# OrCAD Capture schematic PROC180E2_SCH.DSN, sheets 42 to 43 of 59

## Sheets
42 33. POWER SUPPLY FOR ETHERNET: size C; title: POWER SUPPLY (CORE) FOR ETHERNET PHY
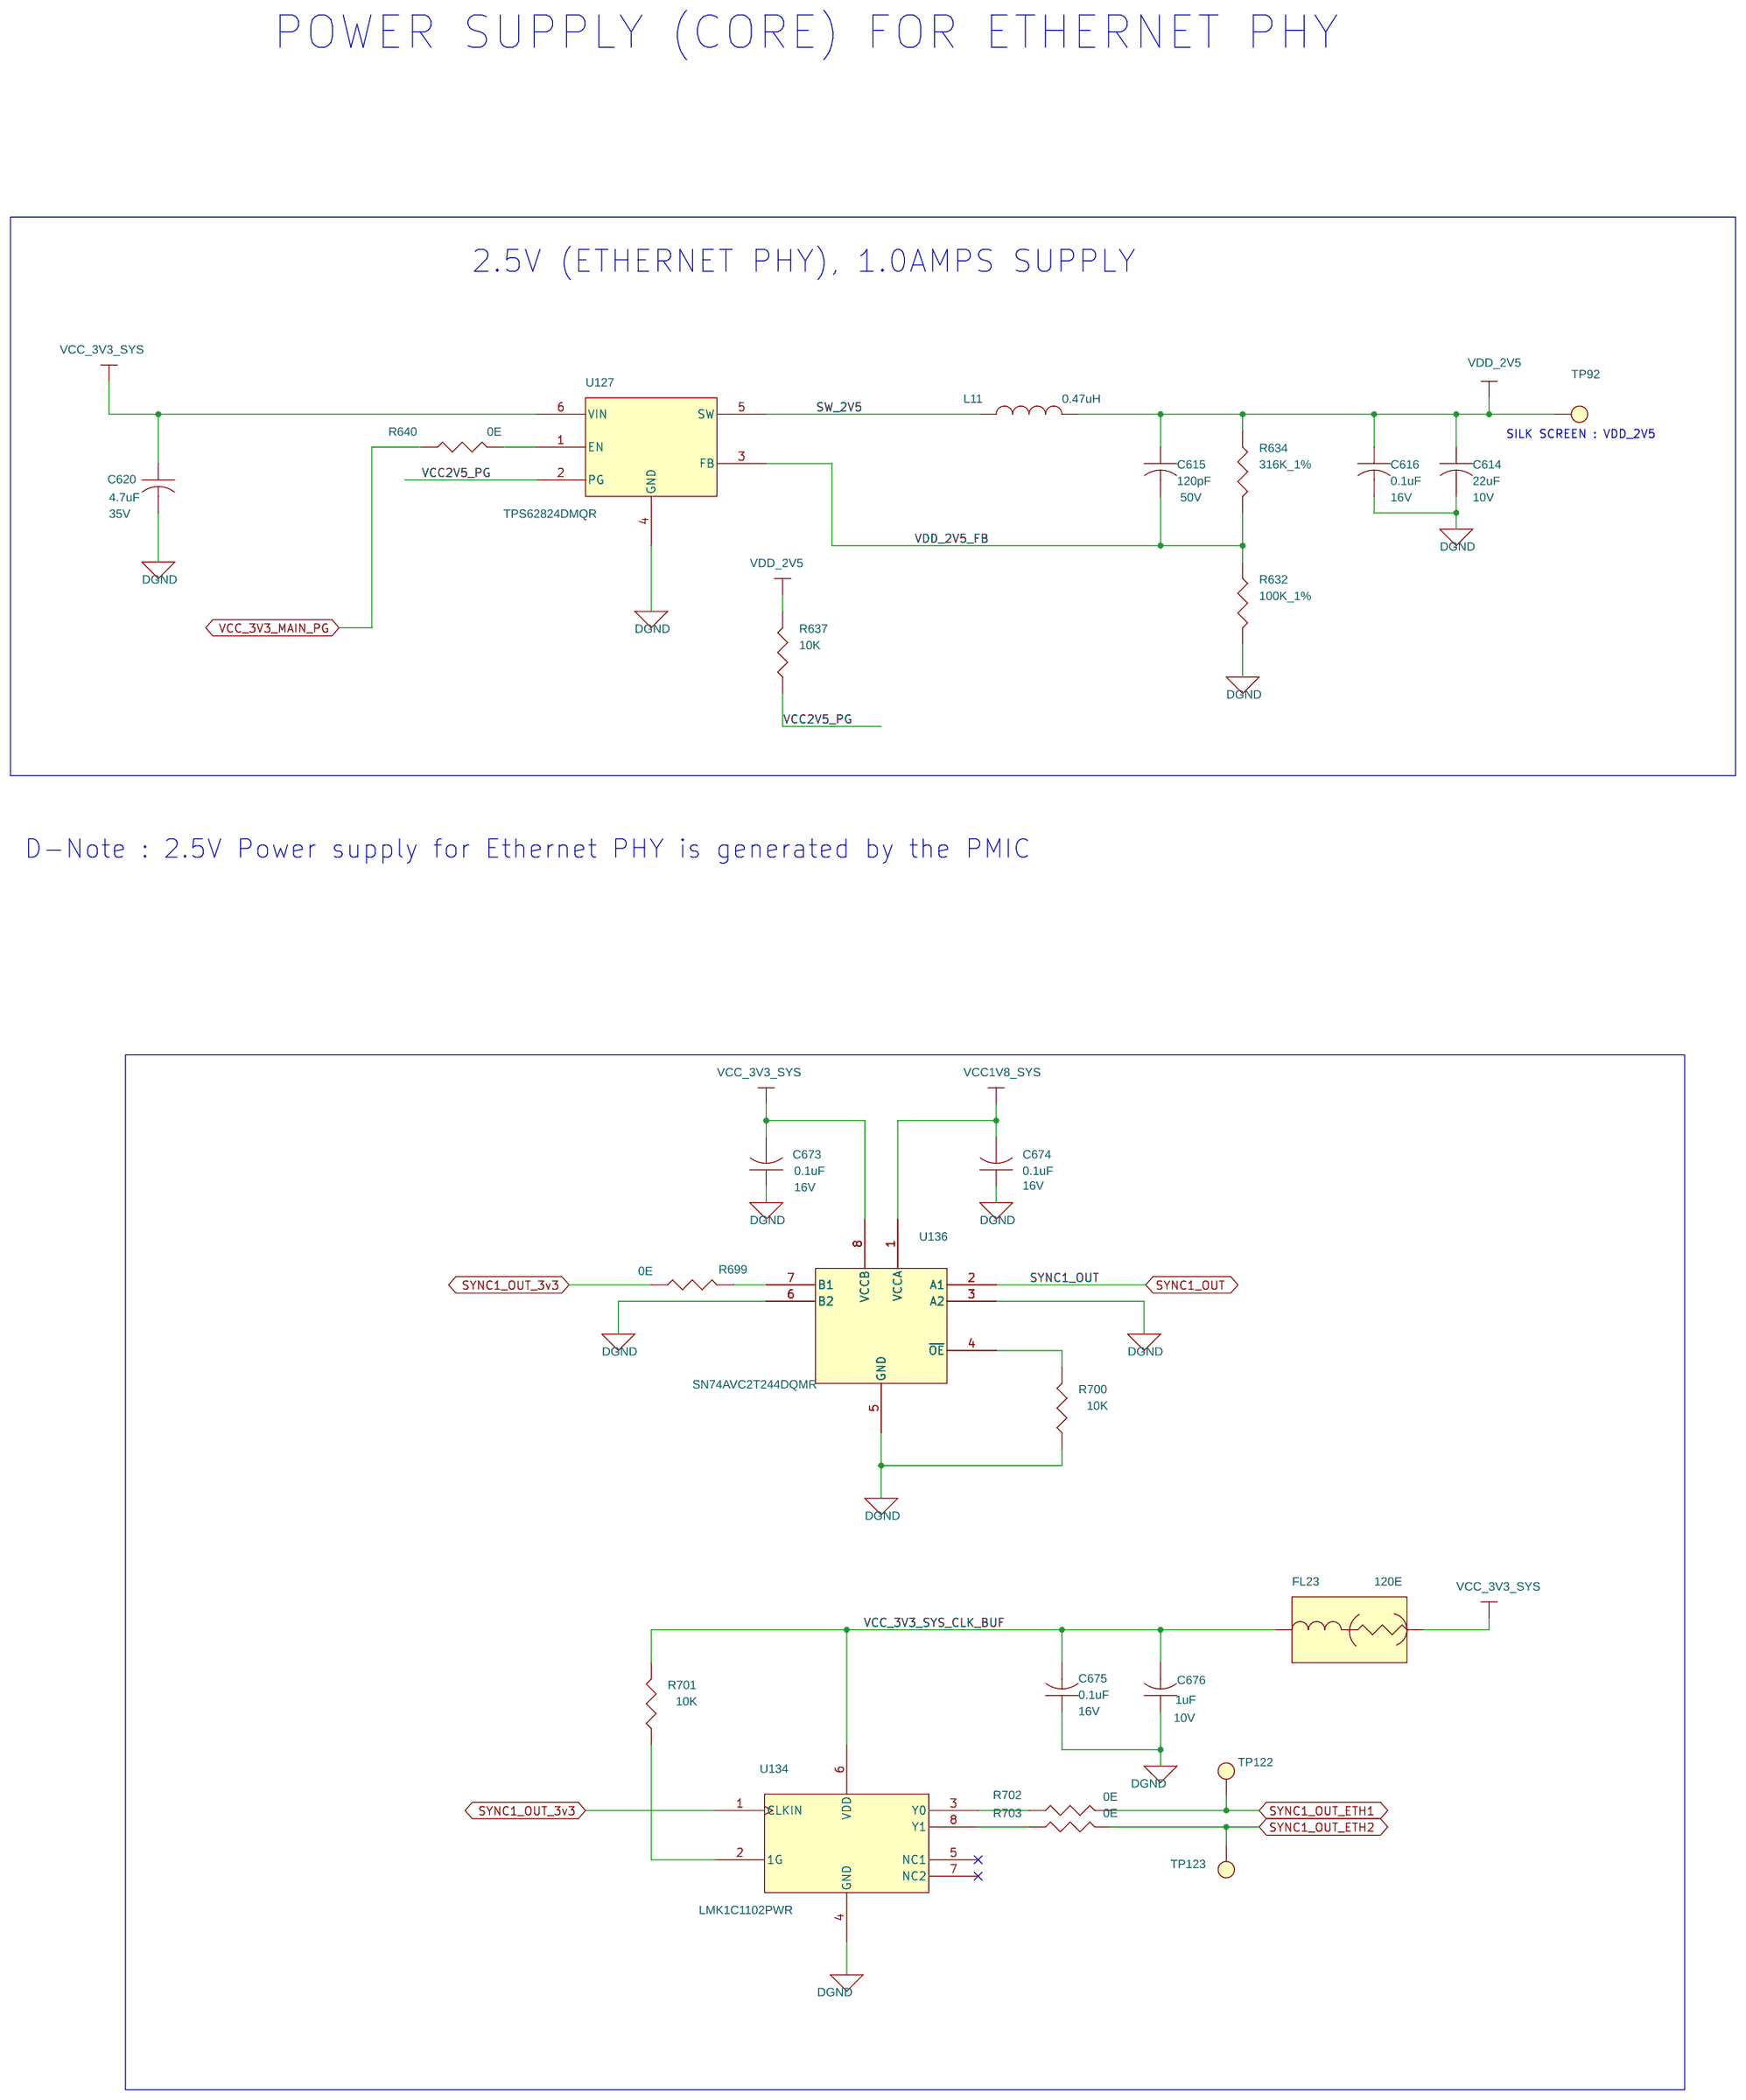
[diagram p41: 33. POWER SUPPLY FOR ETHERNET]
43 48. BOOTMODE BUFFERS AND IO EXP: size C; title: BOOT MODE BUFFER & IO EXPANDERS
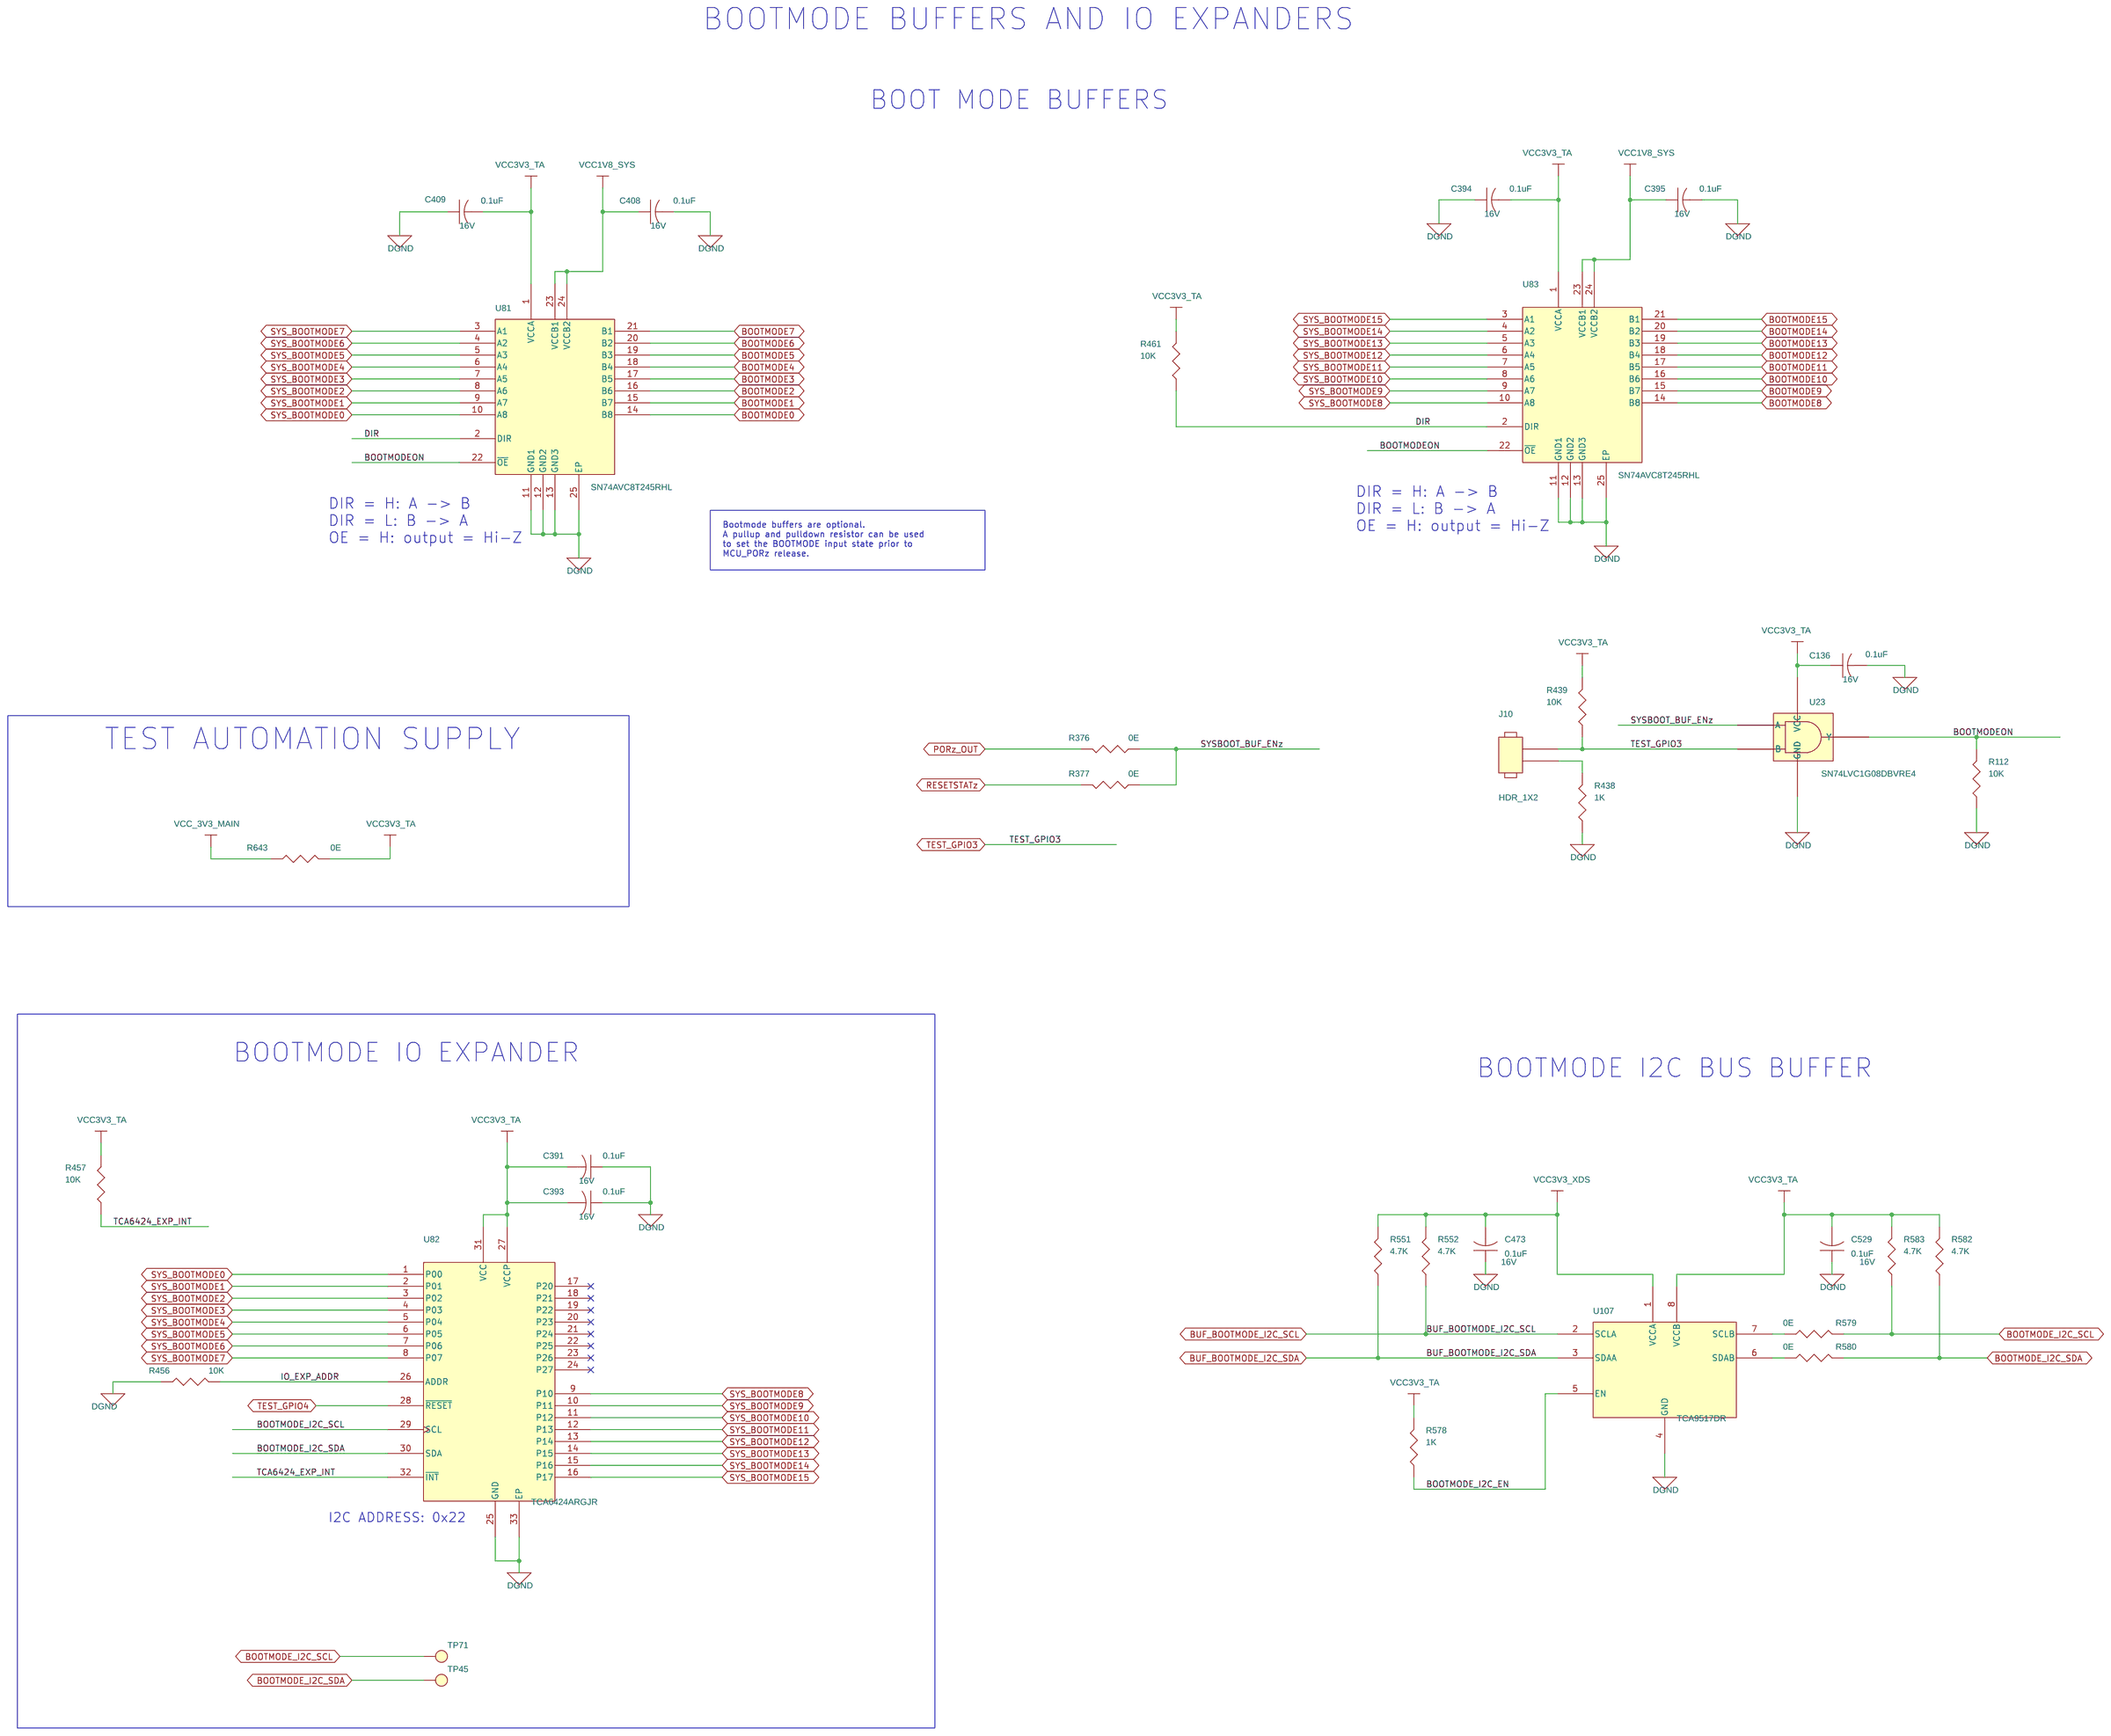
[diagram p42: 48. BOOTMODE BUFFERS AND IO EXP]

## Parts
sheet 33. POWER SUPPLY FOR ETHERNET
C614  22uF  [CAP0603_1]
C615  120pF  [CAP0201_0-5]
C616  0.1uF  [CAP0201_0-5]
C620  4.7uF  [CAP0603_1]
C673  0.1uF  [CAP0201_0-5]
C674  0.1uF  [CAP0201_0-5]
C675  0.1uF  [CAP0201_0-5]
C676  1uF  [CAP0201_0-5]
FL23  120E  [EMIFIL_BLM15A_0402_0-6]
L11  0.47uH  [IND0806_1-2]
R632  100K_1%  [RES0402_0-5]
R634  316K_1%  [RES0402_0-5]
R637  10K  [RES0201_0-5]
R640  0E  [RES0201_0-5]
R699  0E  [RES0201_0-5]
R700  10K  [RES0201_0-5]
R701  10K  [RES0201_0-5]
R702  0E  [RES0201_0-5]
R703  0E  [RES0201_0-5]
TP92  TP20_SMD  [TP20_SMD]
TP122  TP20_SMD  [TP20_SMD]
TP123  TP20_SMD  [TP20_SMD]
U127  TPS62824DMQR  [VSONHR6_TPS62826_60X60_1]
U134  LMK1C1102PWR  [TSSOP8_25-59_125X180_1-2]
U136  SN74AVC2T244DQMR  [X2SON8_15-74_70X50]
sheet 48. BOOTMODE BUFFERS AND IO EXP
C136  0.1uF  [CAP0201_0-5]
C391  0.1uF  [CAP0201_0-5]
C393  0.1uF  [CAP0201_0-5]
C394  0.1uF  [CAP0201_0-5]
C395  0.1uF  [CAP0201_0-5]
C408  0.1uF  [CAP0201_0-5]
C409  0.1uF  [CAP0201_0-5]
C473  0.1uF  [CAP0201_0-5]
C529  0.1uF  [CAP0201_0-5]
J10  HDR_1X2  [HDR_1X2_90120-0122_S_T_5-6]
R112  10K  [RES0201_0-5]
R376  0E  [RES0201_0-5]
R377  0E  [RES0201_0-5]
R438  1K  [RES0201_0-5]
R439  10K  [RES0201_0-5]
R456  10K  [RES0201_0-5]
R457  10K  [RES0201_0-5]
R461  10K  [RES0201_0-5]
R551  4.7K  [RES0201_0-5]
R552  4.7K  [RES0201_0-5]
R578  1K  [RES0402_0-5]
R579  0E  [RES0201_0-5]
R580  0E  [RES0201_0-5]
R582  4.7K  [RES0201_0-5]
R583  4.7K  [RES0201_0-5]
R643  0E  [RES0805_0-75]
TP45  TP20_SMD  [TP20_SMD]
TP71  TP20_SMD  [TP20_SMD]
U23  SN74LVC1G08DBVRE4  [SOT23-5]
U81  SN74AVC8T245RHL  [QFN24_19-68_220X140_1]
U82  TCA6424ARGJR  [QFN32_19-68_200X200]
U83  SN74AVC8T245RHL  [QFN24_19-68_220X140_1]
U107  TCA9517DR  [SOIC8_1-8]

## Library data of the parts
C614 = CAP: CAP CERAMIC 22uF 10V 20% X5R AUTO 0603; Chkd/date: MANIRAJA/250221; Crtd /date: ALVY/240221; Custom_Duty: 15%; Customs_HS_Code: 85369090; Distributor_name: MOUSER; Distributor_part_number: 81-GRT188R61A226ME13; Footprint Path: Y:\MIS_DATABASE\Library\ALTIUM_TOOL\PCB_FOOTPRINTS\Altium_Footprint_Lib.PcbLib; Height: 1.00MM; Library Path: Y:\MIS_DATABASE\Library\ALTIUM_TOOL\SCHEMATICS_PARTS\MS_DISCRETE_Library.schlib; Mfr_name: MURATA; Mfr_part_number: GRT188R61A226ME13D; Mistral Part No: 120021020033-R; Package: 0603; Part_type: CAPACITORS\CERAMIC; Project: TI_DRA821 SK EVM BRD; RoHS: RoHS; Temperature: -55°C+85°C; Tolerance: 20%; Voltage: 10V; Wattage: NA; Weight: NA; Datasheet: Y:\MIS_DATABASE\DATASHEETS\CAPACITORS\GRT188R61A226ME13.PDF
C615 = CAP: CAP CERAMIC 120pF 50V 5% C0G(NP0) AUTO 0201; Chkd/date: MANIRAJA/311221; Crtd /date: ALVY/301221; Custom_Duty: 15%; Customs_HS_Code: 85322990; Distributor_name: MOUSER; Distributor_part_number: 81-GRT0335C1H121JA2D; Footprint Path: Y:\MIS_DATABASE\Library\ALTIUM_TOOL\PCB_FOOTPRINTS\Altium_Footprint_Lib.PcbLib; Height: 0.33MM; Library Path: Y:\MIS_DATABASE\Library\ALTIUM_TOOL\SCHEMATICS_PARTS\MS_DISCRETE_Library.schlib; Mfr_name: MURATA; Mfr_part_number: GRT0335C1H121JA02D; Mistral Part No: 120021120016-R; Package: 0201; Part_type: CAPACITORS\CERAMIC; Project: AM62Q_SKEVM_BRD; RoHS: RoHS; Temperature: -55°C+125°C; Tolerance: 5%; Voltage: 50V; Wattage: NA; Weight: 0.33mg; Datasheet: Y:\MIS_DATABASE\DATASHEETS\CAPACITORS\GRT0335C1H121JA02.PDF
C391 C393 C616 = CAP: CAP CERAMIC 0.1uF 16V 10% X7S AUTO 0201; Chkd/date: MANIRAJA/110321; Crtd /date: ALVY/110321; Custom_Duty: 15%; Customs_HS_Code: 85322990; Distributor_name: DIGIKEY; Distributor_part_number: 490-GRT033C71C104KE01DTR-ND; Footprint Path: Y:\MIS_DATABASE\Library\ALTIUM_TOOL\PCB_FOOTPRINTS\Altium_Footprint_Lib.PcbLib; Height: 0.33MM; Library Path: Y:\MIS_DATABASE\Library\ALTIUM_TOOL\SCHEMATICS_PARTS\MS_DISCRETE_Library.schlib; Mfr_name: MURATA; Mfr_part_number: GRT033C71C104KE01D; Mistral Part No: 120021030007-R; Package: 0201; Part_type: CAPACITORS\CERAMIC; Project: J7ES_SK_BRD; RoHS: RoHS; Temperature: -55°C+125°C; Tolerance: 10%; Voltage: 16V; Wattage: NA; Weight: 330mg; Datasheet: Y:\MIS_DATABASE\DATASHEETS\CAPACITORS\GRT033C71C104KE01.PDF
C620 = CAP: CAP CERAMIC 4.7uF 35V 10% X5R AUTO 0603; Chkd/date: MANIRAJA/311221; Crtd /date: ALVY/301221; Custom_Duty: 15%; Customs_HS_Code: 85369090; Distributor_name: DIGIKEY; Distributor_part_number: 490-12337-1-ND; Footprint Path: Y:\MIS_DATABASE\Library\ALTIUM_TOOL\PCB_FOOTPRINTS\Altium_Footprint_Lib.PcbLib; Height: 1.00MM; Library Path: Y:\MIS_DATABASE\Library\ALTIUM_TOOL\SCHEMATICS_PARTS\MS_DISCRETE_Library.schlib; Mfr_name: MURATA; Mfr_part_number: GRT188R6YA475KE13D; Mistral Part No: 120021120020-R; Package: 0603; Part_type: CAPACITORS\CERAMIC; Project: AM62Q_SKEVM_BRD; RoHS: RoHS; Temperature: -55°C+85°C; Tolerance: 10%; Voltage: 35V; Wattage: NA; Weight: 6.3mg; Datasheet: Y:\MIS_DATABASE\DATASHEETS\CAPACITORS\GRT188R6YA475KE13.PDF
C136 C394 C395 C408 C409 C473 C529 C673-C675 = CAP: CAP CERAMIC 0.1uF 16V 10% X7S AUTO 0201; Alt_Mfr_name: YAGEO AMERICA; Alt_Mfr_part_number: CC0402KRX5R8BB104; Chkd/date: MANIRAJA/110321; Crtd /date: ALVY/110321; Custom_Duty: 15%; Customs_HS_Code: 85322990; Distributor_name: DIGIKEY; Distributor_part_number: 490-GRT033C71C104KE01DTR-ND; Footprint Path: Y:\MIS_DATABASE\Library\ALTIUM_TOOL\PCB_FOOTPRINTS\Altium_Footprint_Lib.PcbLib; Height: 0.33MM; Library Path: Y:\MIS_DATABASE\Library\ALTIUM_TOOL\SCHEMATICS_PARTS\MS_DISCRETE_Library.schlib; Mfr_name: MURATA; Mfr_part_number: GRT033C71C104KE01D; Mistral Part No: 120021030007-R; Package: 0201; Part_type: CAPACITORS\CERAMIC; Project: J7ES_SK_BRD; RoHS: RoHS; Temperature: -55°C+125°C; Tolerance: 10%; Voltage: 16V; Wattage: NA; Weight: 330mg; Datasheet: Y:\MIS_DATABASE\DATASHEETS\CAPACITORS\GRT033C71C104KE01.PDF
C676 = CAP: CAP CERAMIC 1uF 10V 20% X6S 0201; Chkd/date: PRADEEP/130623; Crtd /date: PRADEEP/130623; Custom_Duty: 15%; Customs_HS_Code: 85322990; Distributor_name: DIGIKEY; Distributor_part_number: 490-GRT033C81A105ME13DTR-ND; Footprint Path: Y:\MIS_DATABASE\Library\ALTIUM_TOOL\PCB_FOOTPRINTS\Altium_Footprint_Lib.PcbLib; Height: 0.39MM; Library Path: Y:\MIS_DATABASE\Library\ALTIUM_TOOL\SCHEMATICS_PARTS\MS_DISCRETE_Library.schlib; Mfr_name: MURATA; Mfr_part_number: GRT033C81A105ME13D; Mistral Part No: 120022060020-R; Package: 0201; Part_type: CAPACITORS\CERAMIC; Project: AM62P_SK; RoHS: RoHS; Temperature: -55°C+105°C; Tolerance: 20%; Voltage: 10V; Wattage: NA; Weight: NA; Datasheet: Y:\MIS_DATABASE\DATASHEETS\CAPACITORS\GRT033C81A105ME13D.PDF
FL23 = EMIFILTER_IND: IND FERRITE BEAD CHIP 120E 2A 0402; Chkd/date: MANIRAJA/311221; Crtd /date: ALVY/301221; Custom_Duty: 24%; Customs_HS_Code: 85437099; Distributor_name: NA; Distributor_part_number: NA; Footprint Path: Y:\MIS_DATABASE\Library\ALTIUM_TOOL\PCB_FOOTPRINTS\Altium_Footprint_Lib.PcbLib; Height: 0.55MM; Library Path: Y:\MIS_DATABASE\Library\ALTIUM_TOOL\SCHEMATICS_PARTS\MS_FILTER_Library.schlib; Mfr_name: MURATA; Mfr_part_number: BLM15PX121SZ1B; Mistral Part No: 130021120017-R; Package: 0402; Part_type: INDUCTOR; Project: AM62Q_SKEVM_BRD; RoHS: RoHS; Temperature: -55°C+125°C; Tolerance: 25%; Voltage: NA; Wattage: NA; Weight: 1mg; Datasheet: Y:\MIS_DATABASE\DATASHEETS\DISCRETES\INDUCTORS\BLM-SER.PDF
L11 = INDUCTOR: IND CHIP 0.47uH 3.2A 20% 0806; Chkd/date: MANIRAJA/281221; Crtd /date: ALVY/281221; Custom_Duty: 24%; Customs_HS_Code: 85437099; Distributor_name: DIGIKEY; Distributor_part_number: 490-18076-1-ND; Footprint Path: Y:\MIS_DATABASE\Library\ALTIUM_TOOL\PCB_FOOTPRINTS\Altium_Footprint_Lib.PcbLib; Height: 1.20MM; Library Path: Y:\MIS_DATABASE\Library\ALTIUM_TOOL\SCHEMATICS_PARTS\MS_DISCRETE_Library.schlib; Mfr_name: MURATA; Mfr_part_number: DFE201612PD-R47M=P2; Mistral Part No: 130021120008-R; Package: 0806; Project: AM62Q_SKEVM_BRD; RoHS: RoHS; Temperature: -40°C+125°C; Tolerance: 20%; Voltage: NA; Wattage: NA; Weight: 18.8mg; Datasheet: Y:\MIS_DATABASE\DATASHEETS\DISCRETES\INDUCTORS\DFE201612PD.PDF
R632 = RESISTOR: RES 100K 1/10W 1% 0402; Chkd/date: VASANTHA/201216; Crtd /date: MAZHAR/130306; Custom_Duty: 15%; Customs_HS_Code: 85332119; Distributor_name: DIGIKEY; Distributor_part_number: P100KLCT-ND; Footprint Path: Y:\MIS_DATABASE\Library\ALTIUM_TOOL\PCB_FOOTPRINTS\Altium_Footprint_Lib.PcbLib; Height: 0.40MM; Library Path: Y:\MIS_DATABASE\Library\ALTIUM_TOOL\SCHEMATICS_PARTS\MS_DISCRETE_Library.schlib; Mfr_name: PANASONIC-ECG; Mfr_part_number: ERJ-2RKF1003X; Mistral Part No: 110009030187-R; Package: 0402; Part_type: RESISTORS\FIXED; Project: J32; RoHS: RoHS; Temperature: -55°C+155°C; Tolerance: 1%; Voltage: NA; Wattage: 1/10W; Weight: 0.8mg; Datasheet: Y:\MIS_DATABASE\DATASHEETS\RESISTORS\PAN-ERJSER_NOV17.PDF
R634 = RESISTOR: RES 316K 1/10W 1% 0402; Chkd/date: MAZHAR/110310; Crtd /date: MUDDU/080310; Custom_Duty: 15%; Customs_HS_Code: 85332119; Distributor_name: DIGIKEY; Distributor_part_number: P316KLCT-ND; Footprint Path: Y:\MIS_DATABASE\Library\ALTIUM_TOOL\PCB_FOOTPRINTS\Altium_Footprint_Lib.PcbLib; Height: 0.40MM; Library Path: Y:\MIS_DATABASE\Library\ALTIUM_TOOL\SCHEMATICS_PARTS\MS_DISCRETE_Library.schlib; Mfr_name: PANASONIC-ECG; Mfr_part_number: ERJ-2RKF3163X; Mistral Part No: 110010030027-R; Package: 0402; Part_type: RESISTORS\FIXED; Project: VME_DSP_SUITE; RoHS: RoHS; Temperature: -55°C+155°C; Tolerance: 1%; Voltage: NA; Wattage: 1/10W; Weight: 0.8mg; Datasheet: Y:\MIS_DATABASE\DATASHEETS\RESISTORS\PAN-ERJSER_NOV17.PDF
R112 R439 R456 R457 R461 R637 R700 R701 = RESISTOR: RES 10K 1/20W 5% 0201; Chkd/date: MANIRAJA/050517; Crtd /date: MANIRAJA/050517; Custom_Duty: 15%; Customs_HS_Code: 85332119; Distributor_name: DIGIKEY; Distributor_part_number: 311-10KNCT-ND; Footprint Path: Y:\MIS_DATABASE\Library\ALTIUM_TOOL\PCB_FOOTPRINTS\Altium_Footprint_Lib.PcbLib; Height: 0.26MM; Library Path: Y:\MIS_DATABASE\Library\ALTIUM_TOOL\SCHEMATICS_PARTS\MS_DISCRETE_Library.schlib; Mfr_name: YAGEO AMERICA; Mfr_part_number: RC0201JR-0710KL; Mistral Part No: 110010070051-R; Package: 0201; Part_type: RESISTORS\FIXED; Project: GOLDEN-I LITE; RoHS: RoHS; Temperature: -55°C+125°C; Tolerance: 5%; Voltage: NA; Wattage: 1/20W; Weight: 0.17mg; Datasheet: Y:\MIS_DATABASE\DATASHEETS\RESISTORS\RCXXXXL-SER_MAR18.PDF
R376 R377 R579 R580 R640 R699 R702 R703 = RESISTOR: RES 0E 1/20W 5% 0201; Chkd/date: NAVEED/301214; Crtd /date: MUDDU/120710; Custom_Duty: 15%; Customs_HS_Code: 85332119; Distributor_name: DIGIKEY; Distributor_part_number: 311-0.0NCT-ND; Footprint Path: Y:\MIS_DATABASE\Library\ALTIUM_TOOL\PCB_FOOTPRINTS\Altium_Footprint_Lib.PcbLib; Height: 0.26MM; Library Path: Y:\MIS_DATABASE\Library\ALTIUM_TOOL\SCHEMATICS_PARTS\MS_DISCRETE_Library.schlib; Mfr_name: YAGEO AMERICA; Mfr_part_number: RC0201JR-070RL; Mistral Part No: 110010070067-R; Package: 0201; Part_type: RESISTORS\FIXED; Project: PB_BUGBASE; RoHS: RoHS; Temperature: -55°C+125°C; Tolerance: 5%; Voltage: NA; Wattage: 1/20W; Weight: 0.17mg; Datasheet: Y:\MIS_DATABASE\DATASHEETS\RESISTORS\RCXXXXL-SER_MAR18.PDF
TP92 TP122 TP123 = TESTPOINT: TESTPOINT CIR 20 SMD; Chkd/date: SHREESHAIL/171006; Crtd /date: MAZHAR/171006; Custom_Duty: NA; Customs_HS_Code: NA; Distributor_name: NA; Distributor_part_number: NA; Footprint Path: Y:\MIS_DATABASE\Library\ALTIUM_TOOL\PCB_FOOTPRINTS\Altium_Footprint_Lib.PcbLib; Height: NA; Library Path: Y:\MIS_DATABASE\Library\ALTIUM_TOOL\SCHEMATICS_PARTS\MS_DISCRETE_Library.schlib; MECHANICAL 3D STEP FILE: NA; Manufacturer: LOCAL; Mfr_name: LOCAL; Mistral Part No: NA; Package: SMD; Project: BT MODULE_CSRBC04; RoHS: NA; Temperature: NA; Tolerance: NA; Voltage: NA; Wattage: NA; Weight: NA; Datasheet: NA
U127 = TPS62827DMQR_VSONHR6: IC 1A ADJ STEP-DOWN CONVERTER WITH 1% OUTPUT ACCURACY VSON-HR6; Chkd/date: ALVY/071021; Crtd /date: MANIRAJA/071021; Custom_Duty: 15%; Customs_HS_Code: 85423100; Distributor_name: NA; Distributor_part_number: NA; Footprint Path: Y:\MIS_DATABASE\Library\ALTIUM_TOOL\PCB_FOOTPRINTS\Altium_Footprint_Lib.PcbLib; Height: 1.00MM; Library Path: Y:\MIS_DATABASE\Library\ALTIUM_TOOL\SCHEMATICS_PARTS\MS_MISCPOWER_Library.schlib; Mfr_name: TEXAS INSTRUMENTS; Mistral Part No: 142021100006-R; Package: VSON-HR6; Part_type: ICS\POWER\DC-DC CONVERTER; Project: TI_AM62x SKEVM_BRD; RoHS: RoHS; Temperature: -40°C+125°C; Tolerance: NA; Voltage: NA; Wattage: NA; Weight: NA; Datasheet: Y:\MIS_DATABASE\DATASHEETS\ICS\POWER\TPS6282XX-DEC2020.PDF
U134 = LMK1C1102_TSSOP8: IC LVCMOS CLOCK BUFFER TSSOP8; Chkd/date: PRAVEEN/220922; Crtd /date: PRAVEEN/220922; Custom_Duty: 15%; Customs_HS_Code: 85423100; Distributor_name: DIGIKEY; Distributor_part_number: 296-LMK1C1102PWRCT-ND; Footprint Path: Y:\MIS_DATABASE\Library\ALTIUM_TOOL\PCB_FOOTPRINTS\Altium_Footprint_Lib.PcbLib; Height: 1.20MM; Library Path: Y:\MIS_DATABASE\Library\ALTIUM_TOOL\SCHEMATICS_PARTS\MS_COMBINATIONAL_Library.schlib; Mfr_name: TEXAS INSTRUMENTS; Mistral Part No: 141022090016-R; Package: TSSOP8; Part_type: ICS\DIGITAL\COMBINATIONAL; Project: AM62A_SK_EVM; RoHS: RoHS; Temperature: -40°C+125°C; Tolerance: NA; Voltage: NA; Wattage: NA; Weight: 34.2mg; Datasheet: Y:\MIS_DATABASE\DATASHEETS\ICS\DIGITAL\COMBINATIONAL\LMK1C1104.PDF
U136 = SN74AVC2T244DQMR_X2SON8: IC 2-BIT UNDIRECTIONAL VOLTAGE-LEVEL TRANSLATOR X2SON8; Chkd/date: VASANTHA/060516; Crtd /date: VASANTHA/030316; Customs_HS_Code: 15%; Distributor_name: DIGIKEY; Distributor_part_number: 296-29674-1-ND; Height: 0.40MM; Mfr_name: TEXAS INSTRUMENTS; Mistral Part No: 141016030002-R; Package: X2SON8; Part_type: ICS\INTERFACE\LEVEL TRANSLATOR; Pb-Free: 85423100; Project: OCTASIC_3600; RoHS: RoHS; Temperature: -40°C+85°C; Tolerance: NA; Voltage: NA; Wattage: NA; Weight: NA; Datasheet: Y:\MIS_DATABASE\DATASHEETS\ICS\INTERFACE\SN74AVC2T244.PDF
J10 = HEADER_2X1: CON HDR 1X2 2.54MM PITCH ST TH; Chkd/date: NAVEED/210714; Crtd /date: USMAN/031012; Custom_Duty: 24%; Customs_HS_Code: 85369090; Distributor_name: DIGIKEY; Distributor_part_number: WM8072-ND; Footprint Path: Y:\MIS_DATABASE\Library\ALTIUM_TOOL\PCB_FOOTPRINTS\Altium_Footprint_Lib.PcbLib; Height: 5.60MM; Library Path: Y:\MIS_DATABASE\Library\ALTIUM_TOOL\SCHEMATICS_PARTS\MS_CONNECTOR_Library.schlib; Mfr_name: MOLEX; Mfr_part_number: 90120-0122; Mistral Part No: 150012100005-R; Package: THRU-HOLE; Part_type: CONNECTOR\HEADERS; Project: NPOL_FEP; RoHS: RoHS; Temperature: -55°C+125°C; Tolerance: NA; Voltage: NA; Wattage: NA; Weight: 122mg; Datasheet: Y:\MIS_DATABASE\DATASHEETS\CONNECTORS\90120-XX.PDF
R438 = RESISTOR: RES 1K 1/20W 5% 0201; Chkd/date: MANIRAJA/050517; Crtd /date: MANIRAJA/050517; Custom_Duty: 15%; Customs_HS_Code: 85332119; Distributor_name: DIGIKEY; Distributor_part_number: 311-1KNCT-ND; Footprint Path: Y:\MIS_DATABASE\Library\ALTIUM_TOOL\PCB_FOOTPRINTS\Altium_Footprint_Lib.PcbLib; Height: 0.26MM; Library Path: Y:\MIS_DATABASE\Library\ALTIUM_TOOL\SCHEMATICS_PARTS\MS_DISCRETE_Library.schlib; Mfr_name: YAGEO AMERICA; Mfr_part_number: RC0201JR-071KL; Mistral Part No: 110009030395-R; Package: 0201; Part_type: RESISTORS\FIXED; Project: GOLDEN-I LITE; RoHS: RoHS; Temperature: -55°C+125°C; Tolerance: 5%; Voltage: NA; Wattage: 1/20W; Weight: 0.17mg; Datasheet: Y:\MIS_DATABASE\DATASHEETS\RESISTORS\RCXXXXL-SER_MAR18.PDF
R551 R552 R582 R583 = RESISTOR: RES 4.7K 1/20W 5% 0201; Chkd/date: MANIRAJA/200921; Crtd /date: ALVY/200921; Custom_Duty: 15%; Customs_HS_Code: 85332119; Distributor_name: DIGIKEY; Distributor_part_number: 311-4.7KNCT-ND; Footprint Path: Y:\MIS_DATABASE\Library\ALTIUM_TOOL\PCB_FOOTPRINTS\Altium_Footprint_Lib.PcbLib; Height: 0.26MM; Library Path: Y:\MIS_DATABASE\Library\ALTIUM_TOOL\SCHEMATICS_PARTS\MS_DISCRETE_Library.schlib; Mfr_name: YAGEO AMERICA; Mfr_part_number: RC0201JR-074K7L; Mistral Part No: 110021090007-R; Package: 0201; Part_type: RESISTORS\FIXED; Project: TI_AM62x SKEVM_BRD; RoHS: RoHS; Temperature: -55°C+125°C; Tolerance: 5%; Voltage: NA; Wattage: 1/20W; Weight: 0.17mg; Datasheet: Y:\MIS_DATABASE\DATASHEETS\RESISTORS\RCXXXXL-SER_MAR18.PDF
R578 = RESISTOR: RES 1K 1/10W 5% 0402; Chkd/date: VASANTHA/201216; Crtd /date: MAZHAR/230805; Custom_Duty: 15%; Customs_HS_Code: 85332119; Distributor_name: DIGIKEY; Distributor_part_number: P1.0KJCT-ND; Footprint Path: Y:\MIS_DATABASE\Library\ALTIUM_TOOL\PCB_FOOTPRINTS\Altium_Footprint_Lib.PcbLib; Height: 0.40MM; Library Path: Y:\MIS_DATABASE\Library\ALTIUM_TOOL\SCHEMATICS_PARTS\MS_DISCRETE_Library.schlib; Mfr_name: PANASONIC-ECG; Mfr_part_number: ERJ-2GEJ102X; Mistral Part No: 110009030400-R; Package: 0402; Part_type: RESISTORS\FIXED; Project: HSE; RoHS: RoHS; Temperature: -55°C+155°C; Tolerance: 5%; Voltage: NA; Wattage: 1/10W; Weight: 0.8mg; Datasheet: Y:\MIS_DATABASE\DATASHEETS\RESISTORS\PAN-ERJSER_NOV17.PDF
R643 = RESISTOR: RES 0E 1/8W 5% 0805; Chkd/date: VASANTHA/130416; Crtd /date: JEBRAN/020316; Custom_Duty: 15%; Customs_HS_Code: 85332119; Distributor_name: DIGIKEY; Distributor_part_number: 311-0.0ARCT-ND; Footprint Path: Y:\MIS_DATABASE\Library\ALTIUM_TOOL\PCB_FOOTPRINTS\Altium_Footprint_Lib.PcbLib; Height: 0.60MM; Library Path: Y:\MIS_DATABASE\Library\ALTIUM_TOOL\SCHEMATICS_PARTS\MS_DISCRETE_Library.schlib; Mfr_name: YAGEO AMERICA; Mfr_part_number: RC0805JR-070RL; Mistral Part No: 110009030074-R; Package: 0805; Part_type: RESISTORS\FIXED; Project: ZK_BIOMETRIC; RoHS: RoHS; Temperature: -55°C+155°C; Tolerance: 5%; Voltage: NA; Wattage: 1/8W; Weight: 5.5mg; Datasheet: Y:\MIS_DATABASE\DATASHEETS\RESISTORS\RCXXXXL-SER_MAR18.PDF
TP45 TP71 = TESTPOINT: TESTPOINT CIR 20 SMD; Chkd/date: SHREESHAIL/171006; Crtd /date: MAZHAR/171006; Custom_Duty: NA; Customs_HS_Code: NA; Distributor_name: NA; Distributor_part_number: NA; Footprint Path: Y:\MIS_DATABASE\Library\ALTIUM_TOOL\PCB_FOOTPRINTS\Altium_Footprint_Lib.PcbLib; Height: NA; Library Path: Y:\MIS_DATABASE\Library\ALTIUM_TOOL\SCHEMATICS_PARTS\MS_DISCRETE_Library.schlib; MECHANICAL 3D STEP FILE: NA; Mfr_name: LOCAL; Mistral Part No: NA; Package: SMD; Project: BT MODULE_CSRBC04; RoHS: NA; Temperature: NA; Tolerance: NA; Voltage: NA; Wattage: NA; Weight: NA; Datasheet: NA
U23 = SN74LVC1G08DBVRE4_SOT23-5: IC SINGLE 2-INPUT POSITIVE AND GATE SOT23-5; Chkd/date: SUHAS/221010; Crtd /date: USMAN/151008; Custom_Duty: 15%; Customs_HS_Code: 85423100; Distributor_name: DIGIKEY; Distributor_part_number: SN74LVC1G08DBVRE4-ND; Height: 1.45MM; Mfr_name: TEXAS INSTRUMENTS; Mistral Part No: 141009060026-R; Part_type: ICS\DIGITAL\GATES; Project: KHAN_MAIN; RoHS: Sb/ Br FREE; Temperature: -40°C+85°C; Datasheet: Y:\MIS_DATABASE\DATASHEETS\ICS\DIGITAL\GATES\SN74LVC1G08.PDF
U81 U83 = SN74AVC8T245RHL_QFN24: IC BUS TRANSCEIVER 8-BIT DUAL-SUPPLY QFN24; Chkd/date: VASANTHA/231216; Crtd /date: BAVISH/290411; Custom_Duty: 15%; Customs_HS_Code: 85423100; Distributor_name: DIGIKEY; Distributor_part_number: 296-17859-1-ND; Height: 1.00MM; Mfr_name: TEXAS INSTRUMENTS; Mfr_part_number: SN74AVC8T245RHLR; Mistral Part No: 143011040001-R; Package: QFN24; Part_type: ICS\TELECOM\TRANSCEIVER; Project: OMAPL1_PEC20; RoHS: RoHS; Temperature: -40°C+85°C; Tolerance: NA; Voltage: NA; Wattage: NA; Weight: NA; Datasheet: Y:\MIS_DATABASE\DATASHEETS\ICS\DIGITAL\BUSTRANSCEIVER\SN74AVC8T245.PDF
U82 = TCA6424ARGJR_QFN32: IC I2C I/O EXPANDER 24B UQFN32; Chkd/date: NAVEED/100715; Crtd /date: NAVEED/100914; Custom_Duty: 15%; Customs_HS_Code: 85423100; Distributor_name: DIGIKEY; Distributor_part_number: 296-27844-1-ND; Height: 0.60MM; Mfr_name: TEXAS INSTRUMENTS; Mistral Part No: 141014090009-R; Package: UQFN32; Part_type: ICS\DIGITAL\BUSTRANSCEIVER; Project: ZK_BIOMETRIC; RoHS: RoHS; Temperature: -40°C+85°C; Weight: NA; Datasheet: Y:\MIS_DATABASE\DATASHEETS\ICS\DIGITAL\BUSTRANSCEIVER\TCA6424AR.PDF
U107 = TCA9517DGKR_VSSOP8: IC 2-CHANNEL BI-DIR LEVEL-SHIFTING I2C BUS REPEATER SOIC8; Chkd/date: MANIRAJA/171121; Crtd /date: ALVY/161121; Custom_Duty: 15%; Customs_HS_Code: 85423100; Distributor_name: DIGIKEY; Distributor_part_number: 296-39221-1-ND; Footprint Path: Y:\MIS_DATABASE\Library\ALTIUM_TOOL\PCB_FOOTPRINTS\Altium_Footprint_Lib.PcbLib; Height: 1.75MM; Library Path: Y:\MIS_DATABASE\Library\ALTIUM_TOOL\SCHEMATICS_PARTS\MS_MISCINTERFACE_Library.schlib; Mfr_name: TEXAS INSTRUMENTS; Mistral Part No: 141021110017-R; Package: SOIC8; Part_type: ICS\INTERFACE\LEVEL TRANSLATOR; Project: EXCITER MULTI-CH RX UNIT; RoHS: RoHS; Temperature: -40°C+85°C; Tolerance: NA; Voltage: NA; Wattage: NA; Weight: 540mg; Datasheet: Y:\MIS_DATABASE\DATASHEETS\ICS\INTERFACE\TCA9517.PDF

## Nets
DGND: C136.2 C391.1 C393.1 C394.1 C395.2 C408.2 C409.1 C473.1 C529.1 C614.2 C616.2 C620.2 C673.1 C674.1 C675.1 C676.1 R112.1 R438.1 R456.2 R632.2 R700.2 U23.3(GND) U81.11(GND1) U81.12(GND2) U81.13(GND3) U81.25(EP) U82.25(GND) U82.33(EP) U83.11(GND1) U83.12(GND2) U83.13(GND3) U83.25(EP) U107.4(GND) U127.4(GND) U134.4(GND) U136.3(A2) U136.5(GND) U136.6(B2) ; also on sheet 1 2 3 4 5 6 7 8 9 10 12 13 14 16 17 18 19 20 21 22 31 32 33 34 35 36 37 38 39 40 41 44 45 46 47 48 49 50 51 52 53 54 55 56 57 58
VCC1V8_SYS: C395.1 C408.1 C674.2 U81.23(VCCB1) U81.24(VCCB2) U83.23(VCCB1) U83.24(VCCB2) U136.1(VCCA) ; also on sheet 1 2 4 6 7 10 20 21 22 33 37 38 39 49 50 52 53 54 55 56 57 58
VCC2V5_PG: R637.1 U127.2(PG)
VCC3V3_TA: C136.1 C391.2 C393.2 C394.2 C409.2 C529.2 R439.2 R457.2 R461.2 R578.2 R582.1 R583.1 R643.2 U23.5(VCC) U81.1(VCCA) U82.27(VCCP) U82.31(VCC) U83.1(VCCA) U107.8(VCCB) ; also on sheet 3 9
VCC3V3_XDS: C473.2 R551.1 R552.1 U107.1(VCCA) ; also on sheet 3 44 45
VCC_3V3_MAIN: R643.1 ; also on sheet 2 13 14 32 33
VCC_3V3_MAIN_PG: R640.1 ; also on sheet 32 33
VCC_3V3_SYS: C620.1 C673.2 FL23.2 U127.6(VIN) U136.8(VCCB) ; also on sheet 1 2 3 6 10 14 17 18 19 20 22 31 33 37 38 40 41 45 46 48 49 50 51 52 53 54 55 56 57 58
VCC_3V3_SYS_CLK_BUF: C675.2 C676.2 FL23.1 R701.1 U134.6(VDD)
VDD_2V5: C614.1 C615.1 C616.1 L11.2 R634.1 R637.2 TP92.1(TP) ; also on sheet 40 41
VDD_2V5_FB: C615.2 R632.1 R634.2 U127.3(FB)
BOOTMODE0: U81.14(B8) ; also on sheet 9
BOOTMODE1: U81.15(B7) ; also on sheet 9
BOOTMODE2: U81.16(B6) ; also on sheet 9
BOOTMODE3: U81.17(B5) ; also on sheet 9
BOOTMODE4: U81.18(B4) ; also on sheet 9
BOOTMODE5: U81.19(B3) ; also on sheet 9
BOOTMODE6: U81.20(B2) ; also on sheet 9
BOOTMODE7: U81.21(B1) ; also on sheet 9
BOOTMODE8: U83.14(B8) ; also on sheet 9
BOOTMODE9: U83.15(B7) ; also on sheet 9
BOOTMODE10: U83.16(B6) ; also on sheet 9
BOOTMODE11: U83.17(B5) ; also on sheet 9
BOOTMODE12: U83.18(B4) ; also on sheet 9
BOOTMODE13: U83.19(B3) ; also on sheet 9
BOOTMODE14: U83.20(B2) ; also on sheet 9
BOOTMODE15: U83.21(B1) ; also on sheet 9
BOOTMODE_I2C_EN: R578.1 U107.5(EN)
BOOTMODE_I2C_SCL: R579.1 R583.2 TP71.1(TP) U82.29(SCL)
BOOTMODE_I2C_SDA: R580.1 R582.2 TP45.1(TP) U82.30(SDA)
BOOTMODEON: R112.2 U23.4(Y) U81.22(~{OE}) U83.22(~{OE})
BUF_BOOTMODE_I2C_SCL: R552.2 U107.2(SCLA) ; also on sheet 44
BUF_BOOTMODE_I2C_SDA: R551.2 U107.3(SDAA) ; also on sheet 44
DIR: R461.1 U81.2(DIR) U83.2(DIR)
IO_EXP_ADDR: R456.1 U82.26(ADDR)
PORz_OUT: R376.2 ; also on sheet 10 38 40 41
RESETSTATz: R377.2 ; also on sheet 5 10 37 38 39 40 41 49 55 56
SW_2V5: L11.1 U127.5(SW)
SYNC1_OUT: U136.2(A1) ; also on sheet 7
SYNC1_OUT_3v3: R699.1 U134.1(CLKIN)
SYNC1_OUT_ETH1: R702.2 TP122.1(TP) ; also on sheet 40
SYNC1_OUT_ETH2: R703.2 TP123.1(TP) ; also on sheet 41
SYS_BOOTMODE0: U81.10(A8) U82.1(P00) ; also on sheet 9
SYS_BOOTMODE1: U81.9(A7) U82.2(P01) ; also on sheet 9
SYS_BOOTMODE2: U81.8(A6) U82.3(P02) ; also on sheet 9
SYS_BOOTMODE3: U81.7(A5) U82.4(P03) ; also on sheet 9
SYS_BOOTMODE4: U81.6(A4) U82.5(P04) ; also on sheet 9
SYS_BOOTMODE5: U81.5(A3) U82.6(P05) ; also on sheet 9
SYS_BOOTMODE6: U81.4(A2) U82.7(P06) ; also on sheet 9
SYS_BOOTMODE7: U81.3(A1) U82.8(P07) ; also on sheet 9
SYS_BOOTMODE8: U82.9(P10) U83.10(A8) ; also on sheet 9
SYS_BOOTMODE9: U82.10(P11) U83.9(A7) ; also on sheet 9
SYS_BOOTMODE10: U82.11(P12) U83.8(A6) ; also on sheet 9
SYS_BOOTMODE11: U82.12(P13) U83.7(A5) ; also on sheet 9
SYS_BOOTMODE12: U82.13(P14) U83.6(A4) ; also on sheet 9
SYS_BOOTMODE13: U82.14(P15) U83.5(A3) ; also on sheet 9
SYS_BOOTMODE14: U82.15(P16) U83.4(A2) ; also on sheet 9
SYS_BOOTMODE15: U82.16(P17) U83.3(A1) ; also on sheet 9
SYSBOOT_BUF_ENz: R376.1 R377.1 U23.1(A)
TCA6424_EXP_INT: R457.1 U82.32(~{INT})
TEST_GPIO3: J10.1 R439.1 U23.2(B) ; also on sheet 3
TEST_GPIO4: U82.28(~{RESET}) ; also on sheet 3
N17078974: J10.2 R438.2
N26034689: R640.2 U127.1(EN)
N27248134: R579.2 U107.7(SCLB)
N27248136: R580.2 U107.6(SDAB)
N27857324: R701.2 U134.2(1G)
N27857351: R702.1 U134.3(Y0)
N27857353: R703.1 U134.8(Y1)
N27857372: R700.1 U136.4(~{OE})
N27857388: R699.2 U136.7(B1)

Not connected (* = marked no-connect by the designer): U82 17(P20)* 18(P21)* 19(P22)* 20(P23)* 21(P24)* 22(P25)* 23(P26)* 24(P27)*; U134 5(NC1)* 7(NC2)*

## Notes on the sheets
sheet 42
- POWER SUPPLY (CORE) FOR ETHERNET PHY
- 2.5V (ETHERNET PHY), 1.0AMPS SUPPLY
- SILK SCREEN : VDD_2V5
- D-Note : 2.5V Power supply for Ethernet PHY is generated by the PMIC
sheet 43
- BOOTMODE BUFFERS AND IO EXPANDERS
- BOOT MODE BUFFERS
- DIR = H: A -> B
  DIR = L: B -> A
  OE = H: output = Hi-Z
- DIR = H: A -> B
  DIR = L: B -> A
  OE = H: output = Hi-Z
- Bootmode buffers are optional.
  A pullup and pulldown resistor can be used
  to set the BOOTMODE input state prior to
  MCU_PORz release.
- TEST AUTOMATION SUPPLY
- BOOTMODE IO EXPANDER
- BOOTMODE I2C BUS BUFFER
- I2C ADDRESS: 0x22
